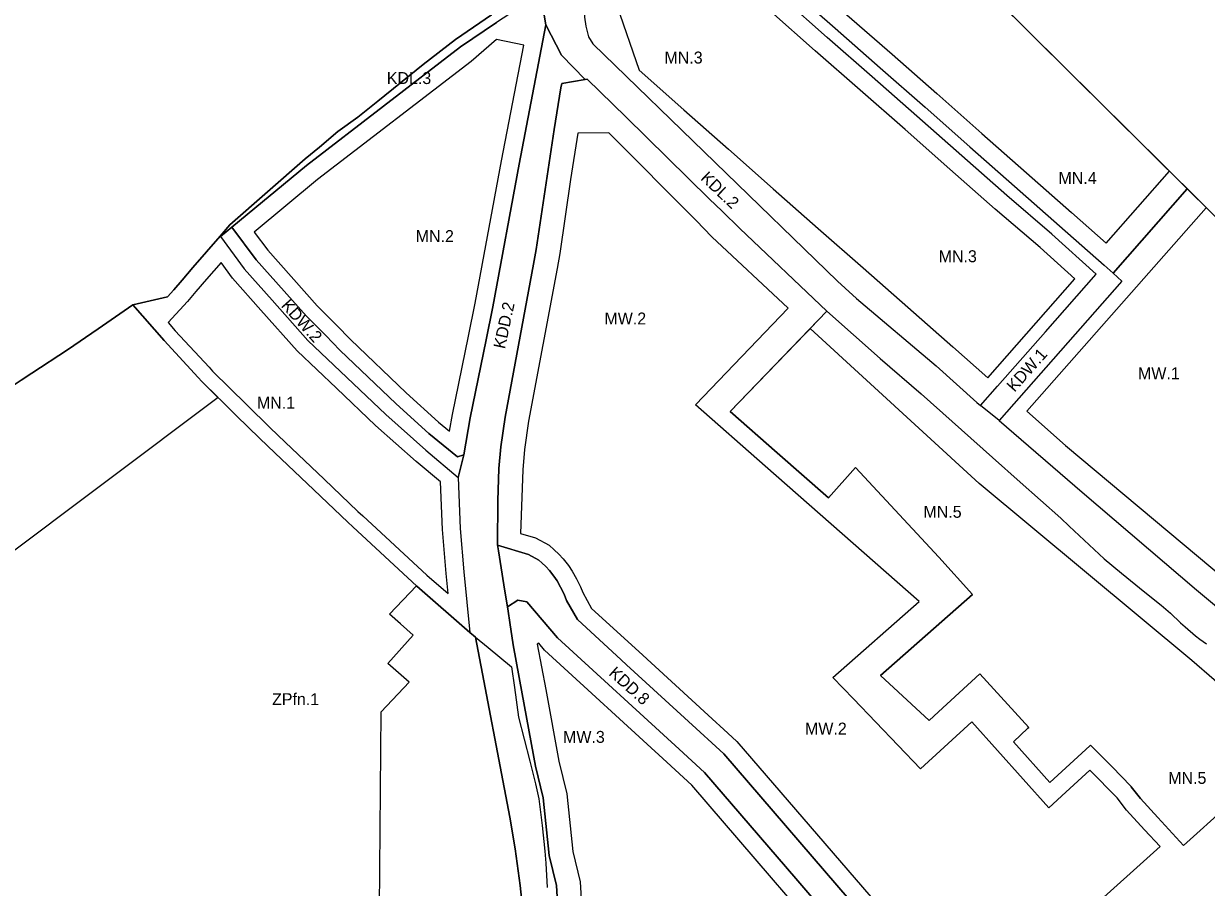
# Model space of a CAD drawing. Extents: x 7432050 to 7433361, y 5551438 to 5552391.
# Drawn here: x 7432631.9 to 7433027.8, y 5551955.2 to 5552244.4 of the extents above; entities that cross this region are included whole.
import ezdxf

# ---------------------------------------------------------------- set-up
doc = ezdxf.new("R2010")
doc.units = 0
for name, color, linetype in [('granica planu', 7, 'Continuous'), ('linie rozgraniczające', 7, 'Continuous'), ('MPZP_Niebyla_Na_Wzgorzach', 7, 'Continuous'), ('nieprzekraczalne linie zabudowy', 7, 'Continuous'), ('oznaczenia przeznaczen', 7, 'Continuous')]:
    doc.layers.add(name, color=color, linetype=linetype)

msp = doc.modelspace()

# ---------------------------------------------------------------- linework, layer by layer
at = {"layer": 'granica planu'}
msp.add_line((7432937.6, 5552272.25), (7433040.46, 5552170.19), dxfattribs=at)
msp.add_lwpolyline([(7432616.71, 5552115.62), (7432634.66, 5552127.39), (7432646.56, 5552135.18), (7432656.84, 5552142.23), (7432662.66, 5552146.26), (7432668.49, 5552150.3), (7432680.09, 5552152.92), (7432682.24, 5552155.28), (7432685.02, 5552158.56), (7432688.59, 5552162.78), (7432697.7, 5552173.28), (7432700.98, 5552177.05), (7432726.14, 5552199.09), (7432730.91, 5552203.01), (7432737.06, 5552208.25), (7432743.76, 5552213.09), (7432750.53, 5552218.5), (7432765.7, 5552230.75), (7432776.42, 5552239.08), (7432788.49, 5552247.32)], dxfattribs=at)
at = {"layer": 'linie rozgraniczające'}
for p, q in [((7433021.35, 5552189.15), (7432937.6, 5552272.25)), ((7432937.6, 5552272.25), (7433040.46, 5552170.19)), ((7432806.73, 5552244.01), (7432805.1, 5552253.38)), ((7432805.1, 5552253.38), (7432806.73, 5552244.01)), ((7432797.73, 5552197.32), (7432806.73, 5552244.01)), ((7432806.73, 5552244.01), (7432797.73, 5552197.32)), ((7432811.71, 5552222.89), (7432812.05, 5552224.33)), ((7432812.05, 5552224.33), (7432811.71, 5552222.89)), ((7432812.05, 5552224.33), (7432819.88, 5552225.69)), ((7432819.88, 5552225.69), (7432812.05, 5552224.33)), ((7432820.56, 5552225.81), (7432819.88, 5552225.69)), ((7432819.88, 5552225.69), (7432820.56, 5552225.81)), ((7432833.51, 5552213.21), (7432820.56, 5552225.81)), ((7432820.56, 5552225.81), (7432833.51, 5552213.21)), ((7432809.53, 5552208.92), (7432811.71, 5552222.89)), ((7432811.71, 5552222.89), (7432809.53, 5552208.92)), ((7432861.32, 5552185.75), (7432833.51, 5552213.21)), ((7432833.51, 5552213.21), (7432861.32, 5552185.75)), ((7432807.1, 5552193.37), (7432809.53, 5552208.92)), ((7432809.53, 5552208.92), (7432807.1, 5552193.37)), ((7432701.58, 5552176.26), (7432726.59, 5552196.93)), ((7432789, 5552149.62), (7432797.73, 5552197.32)), ((7432797.73, 5552197.32), (7432789, 5552149.62)), ((7432961.03, 5552186.87), (7432945.91, 5552200.18)), ((7432803.52, 5552168.81), (7432807.1, 5552193.37)), ((7432807.1, 5552193.37), (7432803.52, 5552168.81)), ((7432996.58, 5552160.88), (7433021.35, 5552189.15)), ((7433021.35, 5552189.15), (7432996.58, 5552160.88)), ((7433040.46, 5552170.19), (7433021.35, 5552189.15)), ((7432865.72, 5552181.6), (7432861.32, 5552185.75)), ((7432861.32, 5552185.75), (7432865.72, 5552181.6)), ((7432976.09, 5552173.94), (7432961.03, 5552186.87)), ((7432697.7, 5552173.28), (7432688.59, 5552162.78)), ((7432697.7, 5552173.28), (7432697.8, 5552173.14)), ((7432697.7, 5552173.28), (7432697.7, 5552173.28)), ((7432701.58, 5552176.26), (7432697.8, 5552173.14)), ((7432697.8, 5552173.14), (7432701.58, 5552176.26)), ((7432697.8, 5552173.14), (7432705.75, 5552162.36)), ((7432701.58, 5552176.26), (7432709.75, 5552165.35)), ((7432709.75, 5552165.35), (7432701.58, 5552176.26)), ((7432802.61, 5552163.92), (7432803.52, 5552168.81)), ((7432803.52, 5552168.81), (7432802.61, 5552163.92)), ((7432688.59, 5552162.78), (7432685.02, 5552158.56)), ((7432705.75, 5552162.36), (7432715.1, 5552151.83)), ((7432793.07, 5552112.63), (7432802.61, 5552163.92)), ((7432802.61, 5552163.92), (7432793.07, 5552112.63)), ((7432999.52, 5552158.2), (7432958.43, 5552111.51)), ((7432996.58, 5552160.88), (7432999.52, 5552158.2)), ((7432668.49, 5552150.3), (7432662.66, 5552146.26)), ((7432680.09, 5552152.92), (7432668.49, 5552150.3)), ((7432678.97, 5552138.26), (7432668.49, 5552150.3)), ((7432786.74, 5552138.58), (7432789, 5552149.62)), ((7432789, 5552149.62), (7432786.74, 5552138.58)), ((7432910.71, 5552152.42), (7432937.34, 5552129.81)), ((7432868.44, 5552114.51), (7432900.78, 5552148.12)), ((7432900.78, 5552148.12), (7432918.57, 5552132.3)), ((7432896.63, 5552143.8), (7432868.44, 5552114.51)), ((7432690.37, 5552125.95), (7432678.97, 5552138.26)), ((7432781.39, 5552112.46), (7432786.74, 5552138.58)), ((7432786.74, 5552138.58), (7432781.39, 5552112.46)), ((7432646.56, 5552135.18), (7432634.66, 5552127.39)), ((7432737.76, 5552135.08), (7432756.57, 5552117.11)), ((7432756.57, 5552117.11), (7432737.76, 5552135.08)), ((7432918.57, 5552132.3), (7432932.32, 5552120.41)), ((7432937.34, 5552129.81), (7432950.93, 5552117.59)), ((7432634.66, 5552127.39), (7432616.71, 5552115.62)), ((7432691.6, 5552124.62), (7432690.37, 5552125.95)), ((7432703.11, 5552113.23), (7432691.6, 5552124.62)), ((7432950.93, 5552117.59), (7432952.21, 5552116.55)), ((7432756.57, 5552117.11), (7432767.51, 5552107.21)), ((7432767.51, 5552107.21), (7432756.57, 5552117.11)), ((7432884.12, 5552100.7), (7432868.44, 5552114.51)), ((7432868.44, 5552114.51), (7432884.12, 5552100.7)), ((7432958.43, 5552111.51), (7432952.21, 5552116.55)), ((7432710.94, 5552105.46), (7432703.11, 5552113.23)), ((7432779.23, 5552100.05), (7432781.39, 5552112.46)), ((7432781.39, 5552112.46), (7432779.23, 5552100.05)), ((7432791.59, 5552102.74), (7432793.07, 5552112.63)), ((7432793.07, 5552112.63), (7432791.59, 5552102.74)), ((7432958.43, 5552111.51), (7432986.21, 5552087.55)), ((7432777.1, 5552099.4), (7432767.51, 5552107.21)), ((7432715.99, 5552100.66), (7432710.94, 5552105.46)), ((7432791.01, 5552095.47), (7432791.59, 5552102.74)), ((7432791.59, 5552102.74), (7432791.01, 5552095.47)), ((7432729.04, 5552088.26), (7432715.99, 5552100.66)), ((7432766.56, 5552101.55), (7432777.38, 5552092.49)), ((7432779.23, 5552100.05), (7432777.1, 5552099.4)), ((7432777.38, 5552092.49), (7432779.23, 5552100.05)), ((7432779.23, 5552100.05), (7432777.38, 5552092.49)), ((7432901.3, 5552085.58), (7432884.12, 5552100.7)), ((7432884.12, 5552100.7), (7432901.3, 5552085.58)), ((7432790.61, 5552084.64), (7432791.01, 5552095.47)), ((7432791.01, 5552095.47), (7432790.61, 5552084.64)), ((7432910.37, 5552095.77), (7432901.3, 5552085.58)), ((7432901.3, 5552085.58), (7432910.37, 5552095.77)), ((7432938.22, 5552065.78), (7432910.37, 5552095.77)), ((7432910.37, 5552095.77), (7432938.22, 5552065.78)), ((7432777.38, 5552092.49), (7432778.06, 5552075.38)), ((7432965.48, 5552090.92), (7432979.02, 5552078.84)), ((7432740.43, 5552077.44), (7432729.04, 5552088.26)), ((7432790.49, 5552069.86), (7432790.61, 5552084.64)), ((7432790.61, 5552084.64), (7432790.49, 5552069.86)), ((7432979.02, 5552078.84), (7432981.86, 5552076.18)), ((7432742.11, 5552075.89), (7432740.43, 5552077.44)), ((7432763.56, 5552056.01), (7432742.11, 5552075.89)), ((7432778.06, 5552075.38), (7432779.3, 5552060.89)), ((7432981.86, 5552076.18), (7432993.55, 5552065.23)), ((7432790.81, 5552067.87), (7432790.49, 5552069.86)), ((7432790.49, 5552069.86), (7432790.5, 5552069.77)), ((7432800.95, 5552066.65), (7432790.5, 5552069.77)), ((7432790.5, 5552069.77), (7432800.95, 5552066.65)), ((7432792.67, 5552056.5), (7432790.81, 5552067.87)), ((7432804.37, 5552064.8), (7432800.95, 5552066.65)), ((7432800.95, 5552066.65), (7432804.37, 5552064.8)), ((7432805.41, 5552063.84), (7432804.37, 5552064.8)), ((7432804.37, 5552064.8), (7432805.41, 5552063.84)), ((7432949.5, 5552053.3), (7432938.22, 5552065.78)), ((7432938.22, 5552065.78), (7432949.5, 5552053.3)), ((7432779.3, 5552060.89), (7432781.27, 5552040.56)), ((7432781.27, 5552040.56), (7432763.56, 5552056.01)), ((7432794.08, 5552047.65), (7432792.67, 5552056.5)), ((7432792.67, 5552056.5), (7432793.84, 5552049.13)), ((7432793.84, 5552049.13), (7432797.35, 5552051.32)), ((7432797.35, 5552051.32), (7432793.84, 5552049.13)), ((7432797.35, 5552051.32), (7432800.35, 5552050.86)), ((7432800.35, 5552050.86), (7432797.35, 5552051.32)), ((7432800.35, 5552050.86), (7432810.62, 5552038.8)), ((7432810.62, 5552038.8), (7432800.35, 5552050.86)), ((7432918.66, 5552026.16), (7432949.5, 5552053.3)), ((7432949.5, 5552053.3), (7432918.66, 5552026.16)), ((7433007.16, 5552054.06), (7433012.66, 5552049.65)), ((7432793.84, 5552049.13), (7432794.08, 5552047.65)), ((7432794.68, 5552043.85), (7432794.08, 5552047.65)), ((7432794.08, 5552047.65), (7432794.68, 5552043.85)), ((7433012.66, 5552049.65), (7433015.72, 5552047.06)), ((7433015.72, 5552047.06), (7433019.13, 5552043.81)), ((7432795.72, 5552036.37), (7432794.68, 5552043.85)), ((7432794.68, 5552043.85), (7432795.72, 5552036.37)), ((7433019.13, 5552043.81), (7433020.67, 5552042.44)), ((7433020.67, 5552042.44), (7433024.1, 5552039.41)), ((7432781.27, 5552040.56), (7432783.18, 5552038.98)), ((7432783.18, 5552038.98), (7432781.27, 5552040.56)), ((7432783.18, 5552038.98), (7432794.66, 5551978.68)), ((7432794.66, 5551978.68), (7432783.18, 5552038.98)), ((7432810.62, 5552038.8), (7432851.32, 5552001.49)), ((7432851.32, 5552001.49), (7432810.62, 5552038.8)), ((7433024.1, 5552039.41), (7433025.56, 5552038.35)), ((7433025.56, 5552038.35), (7433027.78, 5552036.79)), ((7432798.84, 5552020.03), (7432795.72, 5552036.37)), ((7432795.72, 5552036.37), (7432798.84, 5552020.03)), ((7432951.98, 5552026.71), (7432938.11, 5552013.96)), ((7432938.11, 5552013.96), (7432951.98, 5552026.71)), ((7432968.35, 5552008.78), (7432951.98, 5552026.71)), ((7432951.98, 5552026.71), (7432968.35, 5552008.78)), ((7432934.95, 5552011.04), (7432918.66, 5552026.16)), ((7432918.66, 5552026.16), (7432934.95, 5552011.04)), ((7432803.2, 5551995.82), (7432798.84, 5552020.03)), ((7432798.84, 5552020.03), (7432803.2, 5551995.82)), ((7432938.11, 5552013.96), (7432934.95, 5552011.04)), ((7432934.95, 5552011.04), (7432938.11, 5552013.96)), ((7432863.62, 5552002.36), (7432857.04, 5552008.38)), ((7432857.04, 5552008.38), (7432863.62, 5552002.36)), ((7432963.28, 5552003.96), (7432968.01, 5552008.46)), ((7432968.01, 5552008.46), (7432963.28, 5552003.96)), ((7432968.01, 5552008.46), (7432968.35, 5552008.78)), ((7432968.35, 5552008.78), (7432968.01, 5552008.46)), ((7432975.41, 5551990.33), (7432963.28, 5552003.96)), ((7432963.28, 5552003.96), (7432975.41, 5551990.33)), ((7432988.78, 5552002.63), (7432976.72, 5551991.53)), ((7432976.72, 5551991.53), (7432988.78, 5552002.63)), ((7432989.01, 5552002.85), (7432988.78, 5552002.63)), ((7432988.78, 5552002.63), (7432989.01, 5552002.85)), ((7432996.21, 5551995.5), (7432989.01, 5552002.85)), ((7432989.01, 5552002.85), (7432996.21, 5551995.5)), ((7432851.32, 5552001.49), (7432859.84, 5551993.62)), ((7432859.84, 5551993.62), (7432851.32, 5552001.49)), ((7432866.31, 5551999.9), (7432863.62, 5552002.36)), ((7432863.62, 5552002.36), (7432866.31, 5551999.9)), ((7432927.77, 5551928.55), (7432866.31, 5551999.9)), ((7432866.31, 5551999.9), (7432927.77, 5551928.55)), ((7432805.78, 5551985.12), (7432803.2, 5551995.82)), ((7432803.2, 5551995.82), (7432805.78, 5551985.12)), ((7433002.47, 5551989.11), (7432996.21, 5551995.5)), ((7432996.21, 5551995.5), (7433002.47, 5551989.11)), ((7432859.84, 5551993.62), (7432890.38, 5551958.13)), ((7432890.38, 5551958.13), (7432859.84, 5551993.62)), ((7432976.72, 5551991.53), (7432975.41, 5551990.33)), ((7432975.41, 5551990.33), (7432976.72, 5551991.53)), ((7433002.64, 5551988.89), (7433002.47, 5551989.11)), ((7433002.47, 5551989.11), (7433002.64, 5551988.89)), ((7433005.7, 5551984.9), (7433002.64, 5551988.89)), ((7433002.64, 5551988.89), (7433005.7, 5551984.9)), ((7432807.84, 5551965.81), (7432805.78, 5551985.12)), ((7432805.78, 5551985.12), (7432807.84, 5551965.81)), ((7433011.52, 5551978.57), (7433005.7, 5551984.9)), ((7433005.7, 5551984.9), (7433011.52, 5551978.57)), ((7433034.7, 5551982.39), (7433020.1, 5551969.24)), ((7433020.1, 5551969.24), (7433034.7, 5551982.39)), ((7432794.66, 5551978.68), (7432796.47, 5551968.04)), ((7432796.47, 5551968.04), (7432794.66, 5551978.68)), ((7433020.1, 5551969.24), (7433011.52, 5551978.57)), ((7433011.52, 5551978.57), (7433020.1, 5551969.24)), ((7432796.47, 5551968.04), (7432798.13, 5551955.82)), ((7432798.13, 5551955.82), (7432796.47, 5551968.04)), ((7432810.24, 5551955.85), (7432807.84, 5551965.81)), ((7432807.84, 5551965.81), (7432810.24, 5551955.85)), ((7432798.13, 5551955.82), (7432799.6, 5551941.11)), ((7432799.6, 5551941.11), (7432798.13, 5551955.82)), ((7432813.58, 5551897.47), (7432810.24, 5551955.85)), ((7432810.24, 5551955.85), (7432813.58, 5551897.47)), ((7432890.38, 5551958.13), (7432920.91, 5551922.63)), ((7432920.91, 5551922.63), (7432890.38, 5551958.13))]:
    msp.add_line(p, q, dxfattribs=at)
for points in [[(7432854.36, 5552288.93), (7432859.2, 5552283.32), (7432858.54, 5552282.57), (7432873.55, 5552269.32), (7432888.57, 5552256.03), (7432903.52, 5552242.89), (7432918.61, 5552229.66), (7432933.62, 5552216.48), (7432948.61, 5552203.12), (7432963.57, 5552189.99), (7432978.63, 5552176.73), (7432993.55, 5552163.5), (7432996.58, 5552160.88)], [(7432804.58, 5552256.4), (7432799.34, 5552254.24), (7432788.49, 5552247.32), (7432776.42, 5552239.08), (7432765.7, 5552230.75), (7432750.53, 5552218.5), (7432743.76, 5552213.09), (7432737.06, 5552208.25), (7432730.91, 5552203.01), (7432726.14, 5552199.09), (7432700.98, 5552177.05), (7432697.7, 5552173.28)], [(7432915.92, 5552226.62), (7432900.87, 5552239.78), (7432885.98, 5552253.02)], [(7432800.73, 5552251.57), (7432790.14, 5552244.82), (7432778.17, 5552236.64), (7432726.59, 5552196.93), (7432701.58, 5552176.26)], [(7432819.84, 5552249.71), (7432819.62, 5552246.6), (7432820.09, 5552243.56), (7432821.02, 5552239.99)], [(7432616.71, 5552115.62), (7432634.66, 5552127.39), (7432646.56, 5552135.18), (7432656.84, 5552142.23), (7432662.66, 5552146.26), (7432668.49, 5552150.3), (7432680.09, 5552152.92), (7432682.24, 5552155.28), (7432685.02, 5552158.56), (7432688.59, 5552162.78), (7432697.7, 5552173.28), (7432700.98, 5552177.05), (7432726.14, 5552199.09), (7432730.91, 5552203.01), (7432737.06, 5552208.25), (7432743.76, 5552213.09), (7432750.53, 5552218.5), (7432765.7, 5552230.75), (7432776.42, 5552239.08), (7432788.49, 5552247.32)], [(7432726.59, 5552196.93), (7432778.17, 5552236.64), (7432790.14, 5552244.82)], [(7432819.88, 5552225.69), (7432811.95, 5552233.9), (7432806.73, 5552244.01)], [(7432806.73, 5552244.01), (7432811.95, 5552233.9), (7432819.88, 5552225.69)], [(7432821.02, 5552239.99), (7432822.48, 5552237.7), (7432904.31, 5552158.23)], [(7432945.91, 5552200.18), (7432930.9, 5552213.42), (7432915.92, 5552226.62)], [(7432900.78, 5552148.12), (7432871.61, 5552175.87), (7432865.72, 5552181.6)], [(7432865.72, 5552181.6), (7432871.61, 5552175.87), (7432900.78, 5552148.12)], [(7432973.89, 5552141.19), (7432990.93, 5552160.54), (7432976.09, 5552173.94)], [(7432709.75, 5552165.35), (7432726.55, 5552146.46), (7432733.07, 5552139.96), (7432737.76, 5552135.08)], [(7432737.76, 5552135.08), (7432733.07, 5552139.96), (7432726.55, 5552146.46), (7432709.75, 5552165.35)], [(7432685.02, 5552158.56), (7432682.24, 5552155.28), (7432680.09, 5552152.92)], [(7432904.31, 5552158.23), (7432906.9, 5552155.88), (7432910.71, 5552152.42)], [(7432715.1, 5552151.83), (7432727.06, 5552138.35), (7432740.1, 5552125.94)], [(7432662.66, 5552146.26), (7432656.84, 5552142.23), (7432646.56, 5552135.18)], [(7432952.21, 5552116.55), (7432957.89, 5552123.01), (7432973.89, 5552141.19)], [(7432740.1, 5552125.94), (7432753.11, 5552113.5), (7432766.56, 5552101.55)], [(7432932.32, 5552120.41), (7432956.23, 5552099.15), (7432965.48, 5552090.92)], [(7432767.51, 5552107.21), (7432777.1, 5552099.4), (7432779.23, 5552100.05)], [(7432986.21, 5552087.55), (7433024.46, 5552054.84), (7433086.33, 5552003.28)], [(7432790.5, 5552069.77), (7432790.81, 5552067.87), (7432792.67, 5552056.5)], [(7432807.9, 5552061.28), (7432806.7, 5552062.59), (7432805.41, 5552063.84)], [(7432805.41, 5552063.84), (7432806.7, 5552062.59), (7432807.9, 5552061.28)], [(7432993.55, 5552065.23), (7432999.38, 5552060.43), (7433007.16, 5552054.06)], [(7432810.46, 5552057.83), (7432809.41, 5552059.37), (7432807.9, 5552061.28)], [(7432807.9, 5552061.28), (7432809.41, 5552059.37), (7432810.46, 5552057.83)], [(7432831.91, 5552031.42), (7432817.26, 5552044.85), (7432813.67, 5552051.29), (7432812.79, 5552053.37), (7432811.66, 5552055.76), (7432810.46, 5552057.83)], [(7432810.46, 5552057.83), (7432811.66, 5552055.76), (7432812.79, 5552053.37), (7432813.67, 5552051.29), (7432817.26, 5552044.85), (7432831.91, 5552031.42)], [(7432857.04, 5552008.38), (7432833.74, 5552029.75), (7432831.91, 5552031.42)], [(7432831.91, 5552031.42), (7432833.74, 5552029.75), (7432857.04, 5552008.38)]]:
    msp.add_lwpolyline(points, dxfattribs=at)
at = {"layer": 'MPZP_Niebyla_Na_Wzgorzach'}
for points in [[(7432616.71, 5552115.62), (7432634.66, 5552127.39), (7432646.56, 5552135.18), (7432656.84, 5552142.23), (7432662.66, 5552146.26), (7432668.49, 5552150.3), (7432678.97, 5552138.26), (7432690.37, 5552125.95), (7432691.6, 5552124.62), (7432697.04, 5552119.23), (7432510.77, 5551979.37)], [(7432751.07, 5551948.06), (7432751.54, 5552014), (7432760.91, 5552023.88), (7432753.83, 5552030.18), (7432762.36, 5552039.67), (7432758.01, 5552043.39), (7432754.41, 5552046.7), (7432763.38, 5552056.18), (7432763.56, 5552056.01), (7432781.27, 5552040.56), (7432783.18, 5552038.98), (7432787.35, 5552035.56), (7432795.17, 5552029), (7432796.17, 5552022.08), (7432797.61, 5552012.13), (7432801.31, 5551997.4), (7432803.28, 5551989.84), (7432804.34, 5551984.88), (7432805.47, 5551975.95), (7432806.35, 5551967.27), (7432806.67, 5551963.31), (7432807.2, 5551955.16)]]:
    msp.add_lwpolyline(points, dxfattribs=at)
at = {"layer": 'nieprzekraczalne linie zabudowy'}
for p, q in [((7432790.24, 5552239.14), (7432781.7, 5552231.79)), ((7432837.9, 5552228.79), (7432852.88, 5552215.56)), ((7432852.88, 5552215.56), (7432867.88, 5552202.34)), ((7432867.88, 5552202.34), (7432882.83, 5552189.13)), ((7432994.23, 5552170.91), (7433015.41, 5552195.04)), ((7432882.83, 5552189.13), (7432897.83, 5552175.8)), ((7433027.76, 5552182.79), (7432967.72, 5552114.61)), ((7432709.04, 5552174.64), (7432713.63, 5552168.52)), ((7432897.83, 5552175.8), (7432912.86, 5552162.65)), ((7432912.86, 5552162.65), (7432927.87, 5552149.43)), ((7432954.67, 5552125.84), (7432983.74, 5552158.95)), ((7432856.76, 5552116.79), (7432887.86, 5552149.11)), ((7432927.87, 5552149.43), (7432942.9, 5552136.17)), ((7432942.9, 5552136.17), (7432954.67, 5552125.84)), ((7432949.29, 5552010.65), (7432932.09, 5551994.84))]:
    msp.add_line(p, q, dxfattribs=at)
for points in [[(7432875.78, 5552302.01), (7432875.1, 5552301.26), (7432867.15, 5552292.29), (7432863.22, 5552287.85), (7432867.16, 5552283.28), (7432867, 5552283.1), (7432877.52, 5552273.82), (7432892.54, 5552260.53), (7432907.48, 5552247.4), (7432922.57, 5552234.17), (7432937.59, 5552220.97), (7432952.58, 5552207.61), (7432967.53, 5552194.5), (7432982.6, 5552181.23), (7432994.23, 5552170.91)], [(7432851.25, 5552274.25), (7432847.3, 5552269.78), (7432839.34, 5552260.79), (7432830.42, 5552250.47), (7432837.9, 5552228.79)], [(7432983.74, 5552158.95), (7432972.13, 5552169.44), (7432957.09, 5552182.34), (7432941.94, 5552195.68), (7432926.93, 5552208.92), (7432911.96, 5552222.11), (7432896.9, 5552235.28), (7432882.01, 5552248.52), (7432866.94, 5552261.74), (7432856.45, 5552271.04), (7432856.24, 5552270.79), (7432851.25, 5552274.25)], [(7432774.52, 5552107.95), (7432775.5, 5552113.57), (7432780.86, 5552139.78), (7432783.11, 5552150.76), (7432791.83, 5552198.43), (7432799.32, 5552237.26), (7432790.24, 5552239.14)], [(7432781.7, 5552231.79), (7432730.33, 5552192.24), (7432709.04, 5552174.64)], [(7432887.86, 5552149.11), (7432862.21, 5552173.07), (7432856.99, 5552178.45), (7432827.78, 5552207.87), (7432817.43, 5552207.69), (7432815.01, 5552192.17), (7432811.41, 5552167.5), (7432810.47, 5552162.46), (7432800.96, 5552111.31), (7432799.54, 5552101.83), (7432799, 5552095.01), (7432798.21, 5552073.73)], [(7432713.63, 5552168.52), (7432730.19, 5552149.89), (7432736.64, 5552143.46), (7432741.29, 5552138.62), (7432759.98, 5552120.77), (7432770.77, 5552111), (7432774.52, 5552107.95)], [(7432697.99, 5552164.46), (7432693.14, 5552158.88), (7432689.6, 5552154.69), (7432686.75, 5552151.32), (7432680.35, 5552144.29)], [(7432771.44, 5552090.95), (7432763.29, 5552097.76), (7432749.72, 5552109.82), (7432736.65, 5552122.32), (7432723.46, 5552134.87), (7432711.36, 5552148.51), (7432701.86, 5552159.21), (7432697.99, 5552164.46)], [(7432680.35, 5552144.29), (7432682.69, 5552141.6), (7432694.04, 5552129.34), (7432695.19, 5552128.1), (7432706.63, 5552116.78), (7432714.42, 5552109.05), (7432719.43, 5552104.29), (7432732.48, 5552091.89), (7432743.84, 5552081.09), (7432745.51, 5552079.56), (7432766.91, 5552059.73), (7432773.98, 5552053.55)], [(7433022.87, 5552031.16), (7432951.77, 5552090.45), (7432895.17, 5552142.29)], [(7432931.62, 5552050.88), (7432880.16, 5552096.2), (7432856.76, 5552116.79)], [(7432967.72, 5552114.61), (7432980.61, 5552103.12), (7433084.08, 5552016.52), (7433087.19, 5552020.44)], [(7432773.98, 5552053.55), (7432773.32, 5552060.34), (7432772.07, 5552075.01), (7432771.44, 5552090.95)], [(7432798.21, 5552073.73), (7432803.27, 5552072.22), (7432807.87, 5552069.73), (7432809.54, 5552068.2), (7432811.01, 5552066.77), (7432812.47, 5552065.16), (7432814.25, 5552062.92), (7432815.54, 5552061.03), (7432816.97, 5552058.56), (7432818.27, 5552055.82), (7432819.07, 5552053.93), (7432822.03, 5552048.62), (7432837.79, 5552034.17), (7432861.09, 5552012.8), (7432867.67, 5552006.79), (7432870.62, 5552004.09), (7432932.32, 5551932.46), (7432934.8, 5551929.59), (7432936.1, 5551928.41), (7432947.67, 5551918.15), (7432951.82, 5551914.45)], [(7432932.09, 5551994.84), (7432909.7, 5552018.28), (7432902.79, 5552025.51), (7432931.62, 5552050.88)], [(7432804.35, 5552036.91), (7432803.82, 5552036.63)], [(7432803.82, 5552036.63), (7432806.71, 5552021.49), (7432811.03, 5551997.47), (7432813.68, 5551986.49), (7432815.74, 5551967.18), (7432818.18, 5551957.02), (7432821.38, 5551901.2)], [(7432913.74, 5551921.77), (7432855.52, 5551989.44), (7432847.25, 5551997.08), (7432806.3, 5552034.63), (7432804.35, 5552036.91)], [(7433067.81, 5551992.34), (7433022.87, 5552031.16)], [(7433012.27, 5551968.89), (7433007.1, 5551974.51), (7433001.1, 5551981.04), (7432997.93, 5551985.17), (7432988.8, 5551994.49), (7432980.79, 5551987.12), (7432975, 5551981.77), (7432949.29, 5552010.65)], [(7432951.82, 5551914.45), (7432959.08, 5551920.99), (7432973.55, 5551934.02), (7432987.86, 5551946.91), (7433012.27, 5551968.89)]]:
    msp.add_lwpolyline(points, dxfattribs=at)

# ---------------------------------------------------------------- texts
at = {"layer": 'oznaczenia przeznaczen'}
for s, p in [('MN.3', (7432846.41, 5552231.06)), ('KDL.3', (7432753.48, 5552224.19)), ('MN.4', (7432978.29, 5552190.72)), ('MN.2', (7432763.15, 5552171.27)), ('MN.3', (7432938.18, 5552164.53)), ('MW.2', (7432826.32, 5552143.68)), ('MW.1', (7433004.9, 5552125.31)), ('MN.1', (7432710, 5552115.47)), ('MN.5', (7432933.09, 5552078.95)), ('ZPfn.1', (7432715.08, 5552016.21)), ('MW.3', (7432812.47, 5552003.58)), ('MW.2', (7432893.44, 5552006.36)), ('MN.5', (7433015.01, 5551989.85))]:
    msp.add_text(s, height=4, dxfattribs=at).set_placement(p)
for s, rotation, p in [('KDL.2', 316.3955, (7432858.24, 5552192.37)), ('KDW.2', 312.028, (7432717.89, 5552149.84)), ('KDD.2', 77.8933, (7432793.01, 5552135.3)), ('KDW.1', 48.3484, (7432963.55, 5552120.83)), ('KDD.8', 318.0341, (7432827.49, 5552026.5))]:
    msp.add_text(s, height=4, rotation=rotation, dxfattribs=at).set_placement(p)

doc.saveas('drawing.dxf')
